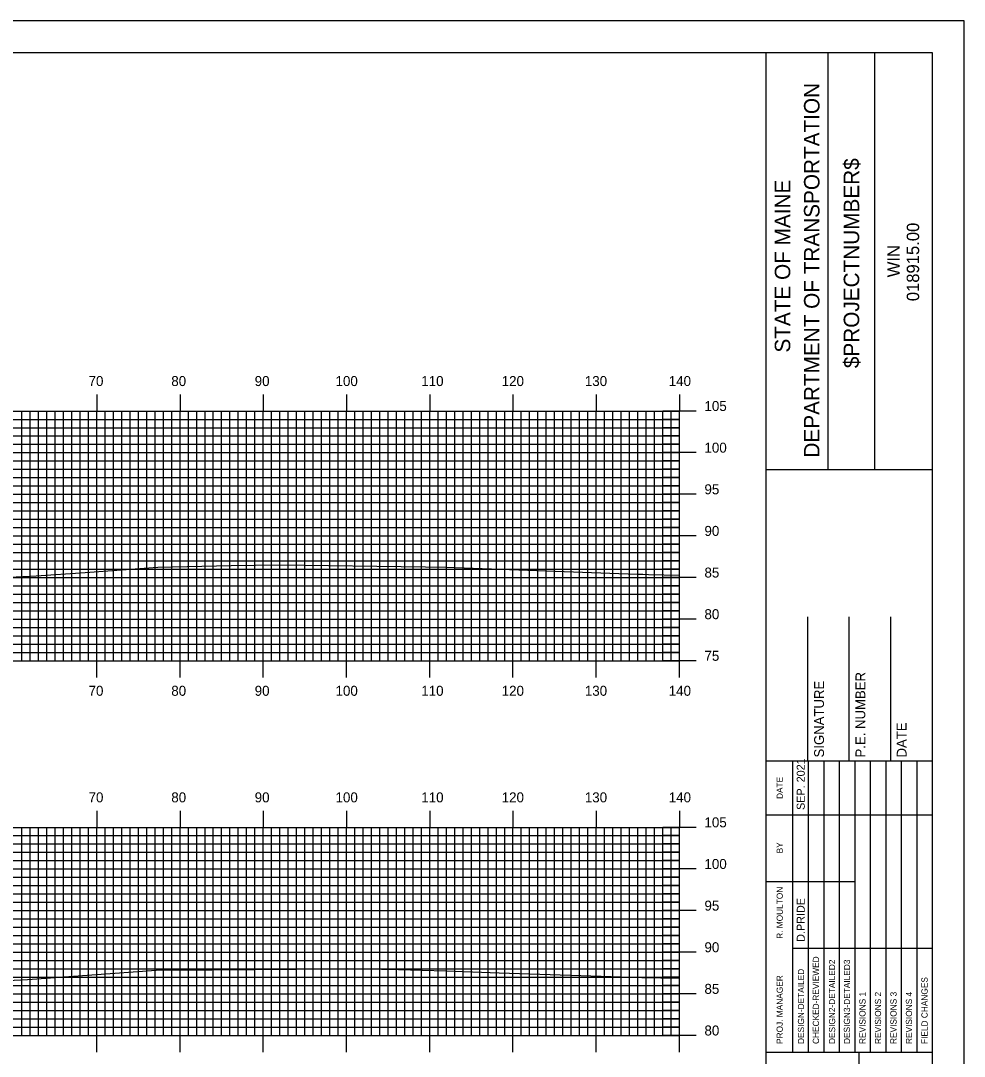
# Model space of a CAD drawing. Extents: x 1775564 to 1775907, y 442591 to 442811.
# Drawn here: x 1775790.6 to 1775903.9, y 442686.2 to 442810.5 of the extents above; entities that cross this region are included whole.
import ezdxf

# ---------------------------------------------------------------- set-up
doc = ezdxf.new("R2010")
doc.units = 0
for name, color, linetype in [('BORDER', 7, 'Continuous'), ('H_V ANNOTATION', 7, 'Continuous'), ('MAJOR', 7, 'Continuous'), ('MINOR', 7, 'Continuous'), ('PLOT BOUNDARY', 7, 'Continuous'), ('S_Roadway_Centerline', 7, 'Continuous')]:
    doc.layers.add(name, color=color, linetype=linetype)

msp = doc.modelspace()

# ---------------------------------------------------------------- linework, layer by layer
at = {"layer": 'BORDER'}
for p, q in [((1775880.11, 442596.67), (1775880.11, 442806.67)), ((1775887.57, 442756.66), (1775887.57, 442806.66)), ((1775893.16, 442756.66), (1775893.16, 442806.66)), ((1775880.11, 442756.65), (1775900.11, 442756.65)), ((1775885.11, 442721.67), (1775885.11, 442738.97)), ((1775890.11, 442721.67), (1775890.11, 442738.97)), ((1775895.11, 442721.67), (1775895.11, 442738.97)), ((1775880.11, 442721.67), (1775900.11, 442721.67)), ((1775880.11, 442686.67), (1775900.11, 442686.67)), ((1775891.29, 442616.67), (1775891.29, 442686.67))]:
    msp.add_line(p, q, dxfattribs=at)
msp.add_lwpolyline([(1775580.11, 442596.67), (1775900.11, 442596.67), (1775900.11, 442806.67), (1775580.11, 442806.67)], close=True, dxfattribs=at)
for points in [[(1775883.34, 442715.17), (1775883.34, 442721.67)], [(1775885.21, 442686.68), (1775885.21, 442721.67)], [(1775887.07, 442721.67), (1775887.07, 442686.68)], [(1775888.93, 442686.68), (1775888.93, 442721.67)], [(1775890.8, 442686.68), (1775890.8, 442721.67)], [(1775892.66, 442686.68), (1775892.66, 442721.67)], [(1775894.52, 442686.68), (1775894.52, 442721.67)], [(1775896.39, 442686.68), (1775896.39, 442721.67)], [(1775898.25, 442686.68), (1775898.25, 442721.67)], [(1775883.34, 442686.68), (1775883.34, 442720.26)], [(1775880.11, 442715.17), (1775900.11, 442715.17)], [(1775880.11, 442707.17), (1775883.34, 442707.17)], [(1775883.34, 442707.17), (1775890.79, 442707.17)], [(1775883.34, 442699.17), (1775900.11, 442699.17)]]:
    msp.add_lwpolyline(points, dxfattribs=at)
at = {"layer": 'MAJOR'}
for p, q in [((1775799.71, 442765.67), (1775799.71, 442763.67)), ((1775809.71, 442765.67), (1775809.71, 442763.67)), ((1775819.71, 442765.67), (1775819.71, 442763.67)), ((1775829.71, 442765.67), (1775829.71, 442763.67)), ((1775839.71, 442765.67), (1775839.71, 442763.67)), ((1775849.71, 442765.67), (1775849.71, 442763.67)), ((1775859.71, 442765.67), (1775859.71, 442763.67)), ((1775869.71, 442765.67), (1775869.71, 442763.67)), ((1775589.71, 442763.67), (1775869.71, 442763.67)), ((1775589.71, 442763.67), (1775869.71, 442763.67)), ((1775799.71, 442733.67), (1775799.71, 442763.67)), ((1775809.71, 442733.67), (1775809.71, 442763.67)), ((1775819.71, 442733.67), (1775819.71, 442763.67)), ((1775829.71, 442733.67), (1775829.71, 442763.67)), ((1775839.71, 442733.67), (1775839.71, 442763.67)), ((1775849.71, 442733.67), (1775849.71, 442763.67)), ((1775859.71, 442733.67), (1775859.71, 442763.67)), ((1775871.72, 442763.67), (1775867.71, 442763.67)), ((1775869.71, 442733.67), (1775869.71, 442763.67)), ((1775869.71, 442733.67), (1775869.71, 442763.67)), ((1775589.71, 442758.67), (1775869.71, 442758.67)), ((1775871.72, 442758.67), (1775867.71, 442758.67)), ((1775589.71, 442753.67), (1775869.71, 442753.67)), ((1775871.72, 442753.67), (1775867.71, 442753.67)), ((1775589.71, 442748.67), (1775869.71, 442748.67)), ((1775871.72, 442748.67), (1775867.71, 442748.67)), ((1775589.71, 442743.67), (1775869.71, 442743.67)), ((1775871.72, 442743.67), (1775867.71, 442743.67)), ((1775589.71, 442738.67), (1775869.71, 442738.67)), ((1775871.72, 442738.67), (1775867.71, 442738.67)), ((1775589.71, 442733.67), (1775869.71, 442733.67)), ((1775589.71, 442733.67), (1775869.71, 442733.67)), ((1775799.71, 442731.66), (1775799.71, 442733.67)), ((1775809.71, 442731.66), (1775809.71, 442733.67)), ((1775819.71, 442731.66), (1775819.71, 442733.67)), ((1775829.71, 442731.66), (1775829.71, 442733.67)), ((1775839.71, 442731.66), (1775839.71, 442733.67)), ((1775849.71, 442731.66), (1775849.71, 442733.67)), ((1775859.71, 442731.66), (1775859.71, 442733.67)), ((1775871.72, 442733.67), (1775867.71, 442733.67)), ((1775869.71, 442731.66), (1775869.71, 442733.67)), ((1775799.71, 442715.67), (1775799.71, 442713.67)), ((1775809.71, 442715.67), (1775809.71, 442713.67)), ((1775819.71, 442715.67), (1775819.71, 442713.67)), ((1775829.71, 442715.67), (1775829.71, 442713.67)), ((1775839.71, 442715.67), (1775839.71, 442713.67)), ((1775849.71, 442715.67), (1775849.71, 442713.67)), ((1775859.71, 442715.67), (1775859.71, 442713.67)), ((1775869.71, 442715.67), (1775869.71, 442713.67)), ((1775589.71, 442713.67), (1775869.71, 442713.67)), ((1775589.71, 442713.67), (1775869.71, 442713.67)), ((1775799.71, 442688.67), (1775799.71, 442713.67)), ((1775809.71, 442688.67), (1775809.71, 442713.67)), ((1775819.71, 442688.67), (1775819.71, 442713.67)), ((1775829.71, 442688.67), (1775829.71, 442713.67)), ((1775839.71, 442688.67), (1775839.71, 442713.67)), ((1775849.71, 442688.67), (1775849.71, 442713.67)), ((1775859.71, 442688.67), (1775859.71, 442713.67)), ((1775871.72, 442713.67), (1775867.71, 442713.67)), ((1775869.71, 442688.67), (1775869.71, 442713.67)), ((1775869.71, 442688.67), (1775869.71, 442713.67)), ((1775589.71, 442708.67), (1775869.71, 442708.67)), ((1775871.72, 442708.67), (1775867.71, 442708.67)), ((1775589.71, 442703.67), (1775869.71, 442703.67)), ((1775871.72, 442703.67), (1775867.71, 442703.67)), ((1775589.71, 442698.67), (1775869.71, 442698.67)), ((1775871.72, 442698.67), (1775867.71, 442698.67)), ((1775589.71, 442693.67), (1775869.71, 442693.67)), ((1775871.72, 442693.67), (1775867.71, 442693.67)), ((1775589.71, 442688.67), (1775869.71, 442688.67)), ((1775589.71, 442688.67), (1775869.71, 442688.67)), ((1775799.71, 442686.66), (1775799.71, 442688.67)), ((1775809.71, 442686.66), (1775809.71, 442688.67)), ((1775819.71, 442686.66), (1775819.71, 442688.67)), ((1775829.71, 442686.66), (1775829.71, 442688.67)), ((1775839.71, 442686.66), (1775839.71, 442688.67)), ((1775849.71, 442686.66), (1775849.71, 442688.67)), ((1775859.71, 442686.66), (1775859.71, 442688.67)), ((1775871.72, 442688.67), (1775867.71, 442688.67)), ((1775869.71, 442686.66), (1775869.71, 442688.67))]:
    msp.add_line(p, q, dxfattribs=at)
at = {"layer": 'MINOR'}
for p, q in [((1775790.71, 442733.67), (1775790.71, 442763.67)), ((1775791.71, 442733.67), (1775791.71, 442763.67)), ((1775792.71, 442733.67), (1775792.71, 442763.67)), ((1775793.71, 442733.67), (1775793.71, 442763.67)), ((1775794.71, 442733.67), (1775794.71, 442763.67)), ((1775795.71, 442733.67), (1775795.71, 442763.67)), ((1775796.71, 442733.67), (1775796.71, 442763.67)), ((1775797.71, 442733.67), (1775797.71, 442763.67)), ((1775798.71, 442733.67), (1775798.71, 442763.67)), ((1775800.71, 442733.67), (1775800.71, 442763.67)), ((1775801.71, 442733.67), (1775801.71, 442763.67)), ((1775802.71, 442733.67), (1775802.71, 442763.67)), ((1775803.71, 442733.67), (1775803.71, 442763.67)), ((1775804.71, 442733.67), (1775804.71, 442763.67)), ((1775805.71, 442733.67), (1775805.71, 442763.67)), ((1775806.71, 442733.67), (1775806.71, 442763.67)), ((1775807.71, 442733.67), (1775807.71, 442763.67)), ((1775808.71, 442733.67), (1775808.71, 442763.67)), ((1775810.71, 442733.67), (1775810.71, 442763.67)), ((1775811.71, 442733.67), (1775811.71, 442763.67)), ((1775812.71, 442733.67), (1775812.71, 442763.67)), ((1775813.71, 442733.67), (1775813.71, 442763.67)), ((1775814.71, 442733.67), (1775814.71, 442763.67)), ((1775815.71, 442733.67), (1775815.71, 442763.67)), ((1775816.71, 442733.67), (1775816.71, 442763.67)), ((1775817.71, 442733.67), (1775817.71, 442763.67)), ((1775818.71, 442733.67), (1775818.71, 442763.67)), ((1775820.71, 442733.67), (1775820.71, 442763.67)), ((1775821.71, 442733.67), (1775821.71, 442763.67)), ((1775822.71, 442733.67), (1775822.71, 442763.67)), ((1775823.71, 442733.67), (1775823.71, 442763.67)), ((1775824.71, 442733.67), (1775824.71, 442763.67)), ((1775825.71, 442733.67), (1775825.71, 442763.67)), ((1775826.71, 442733.67), (1775826.71, 442763.67)), ((1775827.71, 442733.67), (1775827.71, 442763.67)), ((1775828.71, 442733.67), (1775828.71, 442763.67)), ((1775830.71, 442733.67), (1775830.71, 442763.67)), ((1775831.71, 442733.67), (1775831.71, 442763.67)), ((1775832.71, 442733.67), (1775832.71, 442763.67)), ((1775833.71, 442733.67), (1775833.71, 442763.67)), ((1775834.71, 442733.67), (1775834.71, 442763.67)), ((1775835.71, 442733.67), (1775835.71, 442763.67)), ((1775836.71, 442733.67), (1775836.71, 442763.67)), ((1775837.71, 442733.67), (1775837.71, 442763.67)), ((1775838.71, 442733.67), (1775838.71, 442763.67)), ((1775840.71, 442733.67), (1775840.71, 442763.67)), ((1775841.71, 442733.67), (1775841.71, 442763.67)), ((1775842.71, 442733.67), (1775842.71, 442763.67)), ((1775843.71, 442733.67), (1775843.71, 442763.67)), ((1775844.71, 442733.67), (1775844.71, 442763.67)), ((1775845.71, 442733.67), (1775845.71, 442763.67)), ((1775846.71, 442733.67), (1775846.71, 442763.67)), ((1775847.71, 442733.67), (1775847.71, 442763.67)), ((1775848.71, 442733.67), (1775848.71, 442763.67)), ((1775850.71, 442733.67), (1775850.71, 442763.67)), ((1775851.71, 442733.67), (1775851.71, 442763.67)), ((1775852.71, 442733.67), (1775852.71, 442763.67)), ((1775853.71, 442733.67), (1775853.71, 442763.67)), ((1775854.71, 442733.67), (1775854.71, 442763.67)), ((1775855.71, 442733.67), (1775855.71, 442763.67)), ((1775856.71, 442733.67), (1775856.71, 442763.67)), ((1775857.71, 442733.67), (1775857.71, 442763.67)), ((1775858.71, 442733.67), (1775858.71, 442763.67)), ((1775860.71, 442733.67), (1775860.71, 442763.67)), ((1775861.71, 442733.67), (1775861.71, 442763.67)), ((1775862.71, 442733.67), (1775862.71, 442763.67)), ((1775863.71, 442733.67), (1775863.71, 442763.67)), ((1775864.71, 442733.67), (1775864.71, 442763.67)), ((1775865.71, 442733.67), (1775865.71, 442763.67)), ((1775866.71, 442733.67), (1775866.71, 442763.67)), ((1775867.71, 442733.67), (1775867.71, 442763.67)), ((1775868.71, 442733.67), (1775868.71, 442763.67)), ((1775589.71, 442762.67), (1775869.71, 442762.67)), ((1775869.71, 442762.67), (1775867.71, 442762.67)), ((1775589.71, 442761.67), (1775869.71, 442761.67)), ((1775589.71, 442760.67), (1775869.71, 442760.67)), ((1775869.71, 442761.67), (1775867.71, 442761.67)), ((1775869.71, 442760.67), (1775867.71, 442760.67)), ((1775589.71, 442759.67), (1775869.71, 442759.67)), ((1775869.71, 442759.67), (1775867.71, 442759.67)), ((1775589.71, 442757.67), (1775869.71, 442757.67)), ((1775869.71, 442757.67), (1775867.71, 442757.67)), ((1775589.71, 442756.67), (1775869.71, 442756.67)), ((1775589.71, 442755.67), (1775869.71, 442755.67)), ((1775869.71, 442756.67), (1775867.71, 442756.67)), ((1775869.71, 442755.67), (1775867.71, 442755.67)), ((1775589.71, 442754.67), (1775869.71, 442754.67)), ((1775869.71, 442754.67), (1775867.71, 442754.67)), ((1775589.71, 442752.67), (1775869.71, 442752.67)), ((1775869.71, 442752.67), (1775867.71, 442752.67)), ((1775589.71, 442751.67), (1775869.71, 442751.67)), ((1775589.71, 442750.67), (1775869.71, 442750.67)), ((1775869.71, 442751.67), (1775867.71, 442751.67)), ((1775869.71, 442750.67), (1775867.71, 442750.67)), ((1775589.71, 442749.67), (1775869.71, 442749.67)), ((1775869.71, 442749.67), (1775867.71, 442749.67)), ((1775589.71, 442747.67), (1775869.71, 442747.67)), ((1775869.71, 442747.67), (1775867.71, 442747.67)), ((1775589.71, 442746.67), (1775869.71, 442746.67)), ((1775589.71, 442745.67), (1775869.71, 442745.67)), ((1775869.71, 442746.67), (1775867.71, 442746.67)), ((1775869.71, 442745.67), (1775867.71, 442745.67)), ((1775589.71, 442744.67), (1775869.71, 442744.67)), ((1775869.71, 442744.67), (1775867.71, 442744.67)), ((1775589.71, 442742.67), (1775869.71, 442742.67)), ((1775869.71, 442742.67), (1775867.71, 442742.67)), ((1775589.71, 442741.67), (1775869.71, 442741.67)), ((1775589.71, 442740.67), (1775869.71, 442740.67)), ((1775869.71, 442741.67), (1775867.71, 442741.67)), ((1775869.71, 442740.67), (1775867.71, 442740.67)), ((1775589.71, 442739.67), (1775869.71, 442739.67)), ((1775869.71, 442739.67), (1775867.71, 442739.67)), ((1775589.71, 442737.67), (1775869.71, 442737.67)), ((1775869.71, 442737.67), (1775867.71, 442737.67)), ((1775589.71, 442736.67), (1775869.71, 442736.67)), ((1775589.71, 442735.67), (1775869.71, 442735.67)), ((1775869.71, 442736.67), (1775867.71, 442736.67)), ((1775869.71, 442735.67), (1775867.71, 442735.67)), ((1775589.71, 442734.67), (1775869.71, 442734.67)), ((1775869.71, 442734.67), (1775867.71, 442734.67)), ((1775790.71, 442688.67), (1775790.71, 442713.67)), ((1775791.71, 442688.67), (1775791.71, 442713.67)), ((1775792.71, 442688.67), (1775792.71, 442713.67)), ((1775793.71, 442688.67), (1775793.71, 442713.67)), ((1775794.71, 442688.67), (1775794.71, 442713.67)), ((1775795.71, 442688.67), (1775795.71, 442713.67)), ((1775796.71, 442688.67), (1775796.71, 442713.67)), ((1775797.71, 442688.67), (1775797.71, 442713.67)), ((1775798.71, 442688.67), (1775798.71, 442713.67)), ((1775800.71, 442688.67), (1775800.71, 442713.67)), ((1775801.71, 442688.67), (1775801.71, 442713.67)), ((1775802.71, 442688.67), (1775802.71, 442713.67)), ((1775803.71, 442688.67), (1775803.71, 442713.67)), ((1775804.71, 442688.67), (1775804.71, 442713.67)), ((1775805.71, 442688.67), (1775805.71, 442713.67)), ((1775806.71, 442688.67), (1775806.71, 442713.67)), ((1775807.71, 442688.67), (1775807.71, 442713.67)), ((1775808.71, 442688.67), (1775808.71, 442713.67)), ((1775810.71, 442688.67), (1775810.71, 442713.67)), ((1775811.71, 442688.67), (1775811.71, 442713.67)), ((1775812.71, 442688.67), (1775812.71, 442713.67)), ((1775813.71, 442688.67), (1775813.71, 442713.67)), ((1775814.71, 442688.67), (1775814.71, 442713.67)), ((1775815.71, 442688.67), (1775815.71, 442713.67)), ((1775816.71, 442688.67), (1775816.71, 442713.67)), ((1775817.71, 442688.67), (1775817.71, 442713.67)), ((1775818.71, 442688.67), (1775818.71, 442713.67)), ((1775820.71, 442688.67), (1775820.71, 442713.67)), ((1775821.71, 442688.67), (1775821.71, 442713.67)), ((1775822.71, 442688.67), (1775822.71, 442713.67)), ((1775823.71, 442688.67), (1775823.71, 442713.67)), ((1775824.71, 442688.67), (1775824.71, 442713.67)), ((1775825.71, 442688.67), (1775825.71, 442713.67)), ((1775826.71, 442688.67), (1775826.71, 442713.67)), ((1775827.71, 442688.67), (1775827.71, 442713.67)), ((1775828.71, 442688.67), (1775828.71, 442713.67)), ((1775830.71, 442688.67), (1775830.71, 442713.67)), ((1775831.71, 442688.67), (1775831.71, 442713.67)), ((1775832.71, 442688.67), (1775832.71, 442713.67)), ((1775833.71, 442688.67), (1775833.71, 442713.67)), ((1775834.71, 442688.67), (1775834.71, 442713.67)), ((1775835.71, 442688.67), (1775835.71, 442713.67)), ((1775836.71, 442688.67), (1775836.71, 442713.67)), ((1775837.71, 442688.67), (1775837.71, 442713.67)), ((1775838.71, 442688.67), (1775838.71, 442713.67)), ((1775840.71, 442688.67), (1775840.71, 442713.67)), ((1775841.71, 442688.67), (1775841.71, 442713.67)), ((1775842.71, 442688.67), (1775842.71, 442713.67)), ((1775843.71, 442688.67), (1775843.71, 442713.67)), ((1775844.71, 442688.67), (1775844.71, 442713.67)), ((1775845.71, 442688.67), (1775845.71, 442713.67)), ((1775846.71, 442688.67), (1775846.71, 442713.67)), ((1775847.71, 442688.67), (1775847.71, 442713.67)), ((1775848.71, 442688.67), (1775848.71, 442713.67)), ((1775850.71, 442688.67), (1775850.71, 442713.67)), ((1775851.71, 442688.67), (1775851.71, 442713.67)), ((1775852.71, 442688.67), (1775852.71, 442713.67)), ((1775853.71, 442688.67), (1775853.71, 442713.67)), ((1775854.71, 442688.67), (1775854.71, 442713.67)), ((1775855.71, 442688.67), (1775855.71, 442713.67)), ((1775856.71, 442688.67), (1775856.71, 442713.67)), ((1775857.71, 442688.67), (1775857.71, 442713.67)), ((1775858.71, 442688.67), (1775858.71, 442713.67)), ((1775860.71, 442688.67), (1775860.71, 442713.67)), ((1775861.71, 442688.67), (1775861.71, 442713.67)), ((1775862.71, 442688.67), (1775862.71, 442713.67)), ((1775863.71, 442688.67), (1775863.71, 442713.67)), ((1775864.71, 442688.67), (1775864.71, 442713.67)), ((1775865.71, 442688.67), (1775865.71, 442713.67)), ((1775866.71, 442688.67), (1775866.71, 442713.67)), ((1775867.71, 442688.67), (1775867.71, 442713.67)), ((1775868.71, 442688.67), (1775868.71, 442713.67)), ((1775589.71, 442712.67), (1775869.71, 442712.67)), ((1775869.71, 442712.67), (1775867.71, 442712.67)), ((1775589.71, 442711.67), (1775869.71, 442711.67)), ((1775869.71, 442711.67), (1775867.71, 442711.67)), ((1775589.71, 442710.67), (1775869.71, 442710.67)), ((1775589.71, 442709.67), (1775869.71, 442709.67)), ((1775869.71, 442710.67), (1775867.71, 442710.67)), ((1775869.71, 442709.67), (1775867.71, 442709.67)), ((1775589.71, 442707.67), (1775869.71, 442707.67)), ((1775869.71, 442707.67), (1775867.71, 442707.67)), ((1775589.71, 442706.67), (1775869.71, 442706.67)), ((1775869.71, 442706.67), (1775867.71, 442706.67)), ((1775589.71, 442705.67), (1775869.71, 442705.67)), ((1775589.71, 442704.67), (1775869.71, 442704.67)), ((1775869.71, 442705.67), (1775867.71, 442705.67)), ((1775869.71, 442704.67), (1775867.71, 442704.67)), ((1775589.71, 442702.67), (1775869.71, 442702.67)), ((1775869.71, 442702.67), (1775867.71, 442702.67)), ((1775589.71, 442701.67), (1775869.71, 442701.67)), ((1775869.71, 442701.67), (1775867.71, 442701.67)), ((1775589.71, 442700.67), (1775869.71, 442700.67)), ((1775589.71, 442699.67), (1775869.71, 442699.67)), ((1775869.71, 442700.67), (1775867.71, 442700.67)), ((1775869.71, 442699.67), (1775867.71, 442699.67)), ((1775589.71, 442697.67), (1775869.71, 442697.67)), ((1775869.71, 442697.67), (1775867.71, 442697.67)), ((1775589.71, 442696.67), (1775869.71, 442696.67)), ((1775869.71, 442696.67), (1775867.71, 442696.67)), ((1775589.71, 442695.67), (1775869.71, 442695.67)), ((1775589.71, 442694.67), (1775869.71, 442694.67)), ((1775869.71, 442695.67), (1775867.71, 442695.67)), ((1775869.71, 442694.67), (1775867.71, 442694.67)), ((1775589.71, 442692.67), (1775869.71, 442692.67)), ((1775869.71, 442692.67), (1775867.71, 442692.67)), ((1775589.71, 442691.67), (1775869.71, 442691.67)), ((1775869.71, 442691.67), (1775867.71, 442691.67)), ((1775589.71, 442690.67), (1775869.71, 442690.67)), ((1775589.71, 442689.67), (1775869.71, 442689.67)), ((1775869.71, 442690.67), (1775867.71, 442690.67)), ((1775869.71, 442689.67), (1775867.71, 442689.67))]:
    msp.add_line(p, q, dxfattribs=at)
at = {"layer": 'PLOT BOUNDARY'}
msp.add_lwpolyline([(1775563.92, 442590.55), (1775903.92, 442590.55), (1775903.92, 442810.55), (1775563.92, 442810.55)], close=True, dxfattribs=at)
at = {"layer": 'S_Roadway_Centerline'}
for points in [[(1775784.35, 442743.46), (1775792.41, 442743.86), (1775798.31, 442744.29), (1775807.04, 442744.91), (1775815.86, 442745.13), (1775821.7, 442745.19), (1775839.19, 442744.96), (1775841.66, 442744.9), (1775864.61, 442744.08), (1775865.31, 442744.06), (1775865.97, 442744.05), (1775869.71, 442743.95)], [(1775784.1, 442695.04), (1775791.38, 442695.38), (1775806.85, 442696.53), (1775813.53, 442696.54), (1775823.71, 442696.64), (1775829.86, 442696.7), (1775835.94, 442696.58), (1775841.64, 442696.43), (1775848.06, 442696.21), (1775865.19, 442695.62), (1775869.71, 442695.56)]]:
    msp.add_lwpolyline(points, dxfattribs=at)

# ---------------------------------------------------------------- texts
at = {"layer": 'BORDER'}
for s, height, p in [('DEPARTMENT OF TRANSPORTATION', 1.8635, (1775886.53, 442758.08)), ('$PROJECTNUMBER$', 1.8635, (1775891.3, 442768.82)), ('STATE OF MAINE', 1.8635, (1775883.02, 442770.69)), ('018915.00', 1.491, (1775898.5, 442776.86)), ('WIN', 1.491, (1775896.18, 442779.73)), ('P.E. NUMBER', 1.1811, (1775892.03, 442722.06)), ('SIGNATURE', 1.181, (1775887.07, 442722.06)), ('DATE', 1.181, (1775896.99, 442722.06)), ('SEP. 2021', 0.969, (1775884.76, 442715.76)), ('DATE', 0.743, (1775882.12, 442717.08)), ('BY', 0.743, (1775882.12, 442710.54)), ('R. MOULTON', 0.745, (1775882.12, 442700.28)), ('D.PRIDE', 0.969, (1775884.76, 442699.92)), ('CHECKED-REVIEWED', 0.7455, (1775886.47, 442687.65)), ('DESIGN2-DETAILED2', 0.7455, (1775888.41, 442687.65)), ('DESIGN3-DETAILED3', 0.7455, (1775890.2, 442687.65)), ('PROJ. MANAGER', 0.7455, (1775882.12, 442687.65)), ('DESIGN-DETAILED', 0.7455, (1775884.68, 442687.65)), ('FIELD CHANGES', 0.7455, (1775899.52, 442687.65)), ('REVISIONS 1', 0.7455, (1775892.06, 442687.65)), ('REVISIONS 2', 0.7455, (1775893.93, 442687.65)), ('REVISIONS 3', 0.7455, (1775895.79, 442687.65)), ('REVISIONS 4', 0.7455, (1775897.65, 442687.65))]:
    msp.add_text(s, height=height, rotation=90, dxfattribs=at).set_placement(p)
at = {"layer": 'H_V ANNOTATION'}
for s, p in [('70', (1775798.72, 442766.67)), ('80', (1775808.66, 442766.67)), ('90', (1775818.68, 442766.67)), ('100', (1775828.39, 442766.67)), ('110', (1775838.69, 442766.67)), ('120', (1775848.35, 442766.67)), ('130', (1775858.34, 442766.67)), ('140', (1775868.42, 442766.67)), ('105', (1775872.71, 442763.67)), ('100', (1775872.71, 442758.67)), ('95', (1775872.71, 442753.67)), ('90', (1775872.71, 442748.67)), ('85', (1775872.71, 442743.67)), ('80', (1775872.71, 442738.67)), ('75', (1775872.71, 442733.67)), ('70', (1775798.72, 442729.47)), ('80', (1775808.66, 442729.47)), ('90', (1775818.68, 442729.47)), ('100', (1775828.39, 442729.47)), ('110', (1775838.69, 442729.47)), ('120', (1775848.35, 442729.47)), ('130', (1775858.34, 442729.47)), ('140', (1775868.42, 442729.47)), ('70', (1775798.72, 442716.67)), ('80', (1775808.66, 442716.67)), ('90', (1775818.68, 442716.67)), ('100', (1775828.39, 442716.67)), ('110', (1775838.69, 442716.67)), ('120', (1775848.35, 442716.67)), ('130', (1775858.34, 442716.67)), ('140', (1775868.42, 442716.67)), ('105', (1775872.71, 442713.67)), ('100', (1775872.71, 442708.67)), ('95', (1775872.71, 442703.67)), ('90', (1775872.71, 442698.67)), ('85', (1775872.71, 442693.67)), ('80', (1775872.71, 442688.67))]:
    msp.add_text(s, height=1.2, dxfattribs=at).set_placement(p)

doc.saveas('drawing.dxf')
